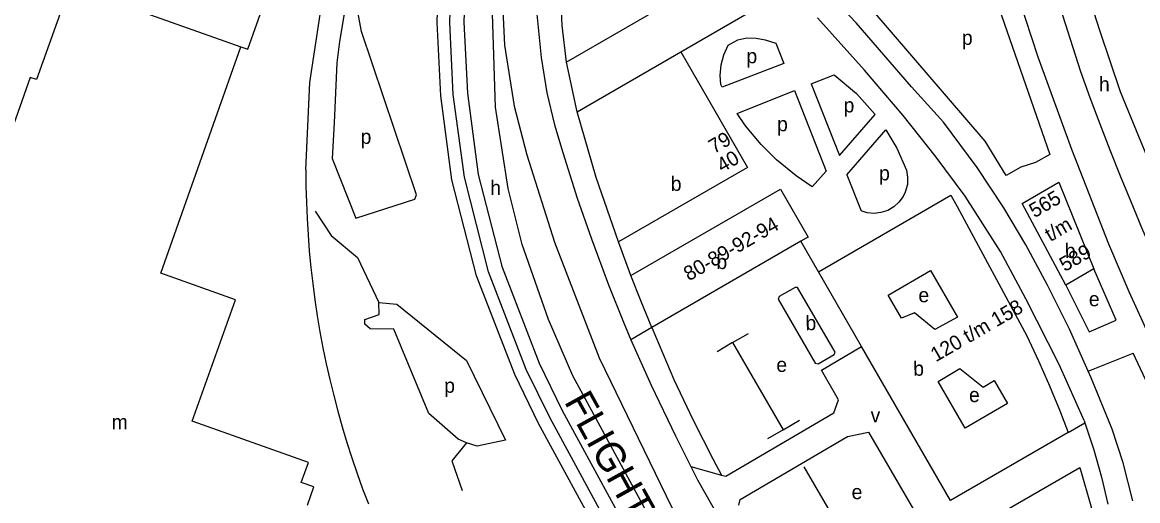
# Model space of a CAD drawing. Extents: x 154765 to 156627, y 383996 to 386132.
# Drawn here: x 155749.2 to 156057.3, y 384900.8 to 385032.8 of the extents above; entities that cross this region are included whole.
import ezdxf

# ---------------------------------------------------------------- set-up
doc = ezdxf.new("R2010")
doc.units = 0
for name, color, linetype in [('BLT_Basislijn', 7, 'Continuous'), ('BLT_Bebouwing', 7, 'Continuous'), ('BLT_Centroide', 7, 'Continuous'), ('BLT_Huisnummer_reeks', 7, 'Continuous'), ('BLT_Onderverdeling_panden', 7, 'Continuous'), ('BLT_Straatnaam_hoofdweg', 7, 'Continuous')]:
    doc.layers.add(name, color=color, linetype=linetype)

msp = doc.modelspace()

# ---------------------------------------------------------------- linework, layer by layer
at = {"layer": 'BLT_Basislijn'}
for p, q in [((156032.54, 385047.32), (156037.29, 385032.48)), ((155979.56, 385032.63), (155967.42, 385045.65)), ((155931.17, 385024.69), (155961.53, 385042.24)), ((155981.88, 385019.64), (155968.89, 385034.02)), ((155994.86, 385015), (155979.56, 385032.63)), ((156037.29, 385032.48), (156041.52, 385019.28)), ((155957.35, 385027.05), (155959.57, 385021.41)), ((155902.48, 385008.1), (155899.6, 385021.83)), ((155992.54, 385007.11), (155981.88, 385019.64)), ((155962.5, 385013.98), (155971.25, 384991.77)), ((155967.14, 385015.83), (155974.95, 384996.02)), ((156003.67, 385005.26), (155994.86, 385015)), ((155974.95, 384996.02), (155984.8, 385007.33)), ((156001.35, 384995.98), (155992.54, 385007.11)), ((156012.95, 384992.73), (156003.67, 385005.26)), ((155977.01, 384990.77), (155987.78, 385003.14)), ((156009.7, 384984.85), (156001.35, 384995.98)), ((155827.56, 384992.1), (155827.59, 384987.61)), ((155967.44, 384987.4), (155971.25, 384991.77)), ((156020.37, 384981.6), (156012.95, 384992.73)), ((155977.01, 384990.77), (155980.93, 384980.83)), ((155827.59, 384987.61), (155827.7, 384983.12)), ((155827.7, 384983.12), (155827.9, 384978.64)), ((156019.44, 384969.54), (156009.7, 384984.85)), ((156026.39, 384971.39), (156020.37, 384981.6)), ((155827.9, 384978.64), (155828.17, 384974.15)), ((155828.17, 384974.15), (155828.52, 384969.68)), ((155917.35, 384962.92), (155913.96, 384972.21)), ((155969.13, 384963.99), (155964.33, 384972.39)), ((156032.42, 384960.26), (156026.39, 384971.39)), ((155828.52, 384969.68), (155828.95, 384965.21)), ((156026.39, 384956.55), (156019.44, 384969.54)), ((155828.95, 384965.21), (155829.46, 384960.74)), ((155829.46, 384960.74), (155830.05, 384956.29)), ((156038.45, 384948.19), (156032.42, 384960.26)), ((155830.05, 384956.29), (155830.72, 384951.85)), ((156035.67, 384938.45), (156026.39, 384956.55)), ((155830.72, 384951.85), (155831.47, 384947.42)), ((155923.15, 384948.61), (155917.34, 384945.23)), ((155831.47, 384947.42), (155832.3, 384943.01)), ((155945.43, 384944.46), (155949.85, 384946.93)), ((156043.66, 384936.57), (156038.45, 384948.19)), ((155832.3, 384943.01), (155833.2, 384938.61)), ((155945.43, 384944.46), (155941.13, 384941.91)), ((155945.43, 384944.46), (155959.44, 384920.41)), ((156043.66, 384936.57), (156056.1, 384941.52)), ((155833.2, 384938.61), (155834.19, 384934.23)), ((156042.53, 384922.93), (156035.67, 384938.45)), ((156044.48, 384934.74), (156043.66, 384936.57)), ((155834.19, 384934.23), (155835.25, 384929.86)), ((156050.3, 384920.53), (156044.48, 384934.74)), ((155835.25, 384929.86), (155836.39, 384925.52)), ((155836.39, 384925.52), (155837.61, 384921.2)), ((155837.61, 384921.2), (155838.9, 384916.9)), ((155959.44, 384920.41), (155963.94, 384923.07)), ((156038.1, 384919.69), (156042.73, 384922.33)), ((156042.53, 384922.93), (156042.73, 384922.33)), ((156042.73, 384922.33), (156045.22, 384914.85)), ((155959.44, 384920.41), (155955.12, 384917.88)), ((156053.29, 384911.26), (156050.3, 384920.53)), ((155838.9, 384916.9), (155840.27, 384912.62)), ((156045.22, 384914.85), (156047.31, 384907.37)), ((155840.27, 384912.62), (155841.71, 384908.37)), ((155841.71, 384908.37), (155843.24, 384904.14)), ((155933.89, 384910.23), (155942.38, 384907.89)), ((155965.14, 384910.17), (155976.62, 384890.53)), ((156055.98, 384900.79), (156053.29, 384911.26)), ((156047.31, 384907.37), (156049.11, 384899.9)), ((155843.24, 384904.14), (155844.83, 384899.94))]:
    msp.add_line(p, q, dxfattribs=at)
for points in [[(155827.56, 384992.1), (155828.67, 385016.24), (155832.77, 385043.5), (155836.07, 385057.7), (155841.73, 385076.19), (155764.26, 385112.84)], [(155892.58, 385086.86), (155891.45, 385078.57), (155891.02, 385071.73), (155890.79, 385047.47), (155891.38, 385035.08), (155892.56, 385023.09), (155894.14, 385013.39), (155896.21, 385004.48)], [(155962.52, 384826.27), (155935.77, 384871.91), (155901.3, 384935.31), (155901.3, 384935.31), (155894.58, 384950.8), (155887.34, 384971.47), (155883.48, 384986.96), (155879.92, 385009.42), (155878.55, 385052.4), (155881.91, 385077.92)], [(155881.91, 385077.92), (155881.11, 385062.39), (155881.31, 385049.86), (155882.44, 385026.52), (155885.1, 385009.65), (155885.1, 385009.65), (155888.56, 384996.23), (155896.24, 384972.11), (155908.62, 384940.24), (155908.62, 384940.24), (155928.62, 384898.94), (155951.25, 384859.63), (155970.21, 384827.91), (155980.73, 384813.62), (155980.73, 384813.62)], [(156061.74, 384943.77), (156054.93, 384958.46), (156049.32, 384971.64), (156039.1, 384997.76), (156029.81, 385023.21), (156021.05, 385049.93), (156014.47, 385072.85)], [(155982.74, 384747.99), (155981.79, 384761.81), (155978.09, 384773), (155961.45, 384799.64), (155934.97, 384845.54), (155909.95, 384888.82), (155891.81, 384922.17), (155885.25, 384935.64), (155874.71, 384962.88), (155867.9, 384989.38), (155864.81, 385012.56), (155863.83, 385032.74), (155864.43, 385050.58)], [(155965.34, 384800.02), (155964.45, 384801.44), (155938, 384847.29), (155913, 384890.54), (155894.92, 384923.78), (155888.46, 384937.04), (155878.05, 384963.95), (155871.35, 384990.05), (155868.3, 385012.88), (155867.33, 385032.77), (155867.93, 385050.46)], [(155968.54, 384801.65), (155941.46, 384849.29), (155916.49, 384892.49), (155898.47, 384925.61), (155892.13, 384938.64), (155881.86, 384965.17), (155875.28, 384990.81), (155872.29, 385013.24), (155871.33, 385032.8), (155871.93, 385050.32)], [(156015.93, 385045.61), (156033.06, 384996.37), (156029.14, 384994.1), (156025.03, 384992.84), (156021.02, 384990.55), (156015.24, 385000), (155984.29, 385035.94)], [(156136, 384858.96), (156115.57, 384891.11), (156096.29, 384922.61), (156080.28, 384952.51), (156069.18, 384974.46), (156063, 384988.46), (156057.67, 385001.26), (156052.62, 385013.66), (156046.98, 385030.26), (156042.75, 385043.48)], [(155959.57, 385021.41), (155942.59, 385014.88), (155942.15, 385015.66), (155941.98, 385018.14), (155942.26, 385021.1), (155943.01, 385023.86), (155944.21, 385026.46), (155946.84, 385027.98), (155949.37, 385028.48), (155951.98, 385028.47), (155954.4, 385027.96), (155957.35, 385027.05)], [(156041.52, 385019.28), (156044.14, 385012.03), (156046.84, 385004.82), (156049.62, 384997.63), (156052.47, 384990.47), (156055.39, 384983.34), (156058.39, 384976.24), (156061.46, 384969.18), (156064.6, 384962.14), (156067.82, 384955.14), (156071.11, 384948.18), (156074.47, 384941.24), (156077.9, 384934.35), (156081.41, 384927.48), (156084.99, 384920.66), (156088.63, 384913.87), (156092.35, 384907.12), (156095.68, 384901.22)], [(155967.14, 385015.83), (155973.46, 385018.35), (155979.63, 385013.14), (155984.8, 385007.33)], [(155967.44, 384987.4), (155962.98, 384990.41), (155957.55, 384994.85), (155953.29, 384999.07), (155948.97, 385004.24), (155946.74, 385007.69), (155962.5, 385013.98)], [(155896.21, 385004.48), (155898.51, 384996.87), (155902.55, 384984.3), (155906.47, 384973.07), (155911.19, 384960.36), (155915.31, 384950.04), (155917.34, 384945.23)], [(155987.78, 385003.14), (155990.76, 384998.07), (155993.45, 384992), (155993.79, 384990.04), (155993.71, 384988.1), (155993.13, 384985.95), (155992.53, 384984.73), (155991.37, 384983.16), (155989.94, 384981.87), (155988.28, 384980.92), (155986.42, 384980.31), (155984.56, 384980.1), (155982.62, 384980.29), (155980.93, 384980.83)], [(155830.1, 384980.75), (155834.6, 384974), (155841.8, 384967.92), (155847.72, 384955.47)], [(156037.46, 384960.3), (156043.92, 384947.46), (156051.35, 384950.63), (156045.21, 384964.78)], [(155871.92, 384916.82), (155869.67, 384917.77), (155861.57, 384924.92), (155851.84, 384948.19), (155845.31, 384948.24), (155843.87, 384949.5), (155843.84, 384950.84), (155847.79, 384952.22), (155847.72, 384955.47)], [(155847.72, 384955.47), (155852.69, 384955.07), (155871.91, 384939.53), (155882.7, 384917.5), (155874.93, 384915.89), (155871.92, 384916.82)], [(155923.15, 384948.61), (155929.17, 384934.24), (155934.53, 384923.04), (155939.97, 384912.36), (155942.38, 384907.89)], [(155917.34, 384945.23), (155922.9, 384932.71), (155929.65, 384918.72), (155933.89, 384910.23)], [(155942.38, 384907.89), (155943.56, 384907.56), (155973.41, 384925.06), (155974.69, 384928.7), (155969.95, 384936.86), (155981.05, 384943.38)], [(156065.34, 384815.35), (156069.84, 384817.65), (156076.45, 384821.69), (156082.14, 384826.94), (156086.82, 384832.59), (156090.38, 384838.99), (156091.74, 384842.55), (156092.79, 384846.44), (156093.42, 384850.35), (156093.66, 384854.23), (156092.91, 384861.91), (156091.4, 384869.47), (156089.18, 384876.95), (156086.34, 384884.21), (156078.11, 384900.51), (156063.66, 384925.43), (156056.1, 384941.52)], [(155947.12, 384899.61), (155947.5, 384901.16), (155977.2, 384918.58), (155983.01, 384919.78), (155997.35, 384895.09), (155982.3, 384886.45), (155983.87, 384882.97), (155964.19, 384869.82)], [(155871.92, 384916.82), (155867.9, 384911.8), (155870.71, 384903.68)], [(155933.89, 384910.23), (155935.71, 384906.61), (155943.51, 384892.95), (155944.9, 384890.58)]]:
    msp.add_lwpolyline(points, dxfattribs=at)
msp.add_lwpolyline([(155840.44, 385043.65), (155838.09, 385034.59), (155836.86, 385027.54), (155836.08, 385021.6), (155835.43, 385005.08), (155834.83, 384995.23), (155841.38, 384978.78), (155857.63, 384984), (155858.17, 384985.25), (155842.94, 385030.24)], close=True, dxfattribs=at)
at = {"layer": 'BLT_Bebouwing'}
msp.add_line((156045.22, 384964.78), (156037.46, 384960.3), dxfattribs=at)
for points in [[(155809.65, 385026.03), (155811.53, 385025.36), (155824.79, 385062.76), (155777.02, 385090.13)], [(155899.6, 385021.83), (155898.36, 385031.96), (155897.72, 385045.37), (155897.61, 385063.18), (155898.17, 385073.01), (155898.47, 385075.8)], [(155898.47, 385075.8), (155907.47, 385071.11), (155922.15, 385062.79), (155935.76, 385054.02), (155940.18, 385050.9), (155944.6, 385047.79), (155899.6, 385021.83)], [(155762.36, 385042.82), (155753.18, 385017), (155751.43, 385017.62), (155744.64, 384998.23), (155746.3, 384997.64), (155740.17, 384980.4), (155738.59, 384980.96), (155696.77, 384862.93)], [(155827.99, 384899.57), (155829.8, 384904.65), (155826.31, 384905.89), (155828.26, 384911.34), (155796.18, 384922.73), (155808.14, 384956.27), (155787.49, 384963.57), (155809.65, 385026.03)], [(155902.48, 385008.1), (155931.17, 385024.69)], [(155931.17, 385024.69), (155949.58, 384992.77), (155913.96, 384972.21)], [(155913.96, 384972.21), (155907.76, 384989.99), (155902.48, 385008.1)], [(156037.46, 384960.3), (156025.39, 384982.81), (156035.57, 384988.69), (156045.22, 384964.78)], [(155917.35, 384962.92), (155958.63, 384986.76), (155966.28, 384973.52), (155965.8, 384973.23), (155964.33, 384972.39)], [(155969.13, 384963.99), (156005.74, 384985.14)], [(156005.74, 384985.14), (156007.45, 384982), (156026.73, 384946.33), (156029.93, 384939.46), (156032.74, 384933.14), (156035.72, 384925.89), (156038.1, 384919.69)], [(155964.33, 384972.39), (155923.15, 384948.61)], [(155981.05, 384943.38), (155969.13, 384963.99)], [(155923.15, 384948.61), (155920.18, 384955.74), (155917.35, 384962.92)], [(156038.1, 384919.69), (156005.6, 384900.89), (155981.05, 384943.38)]]:
    msp.add_lwpolyline(points, dxfattribs=at)
for points in [[(155988.42, 384957.57), (156000.13, 384964.36), (156007.58, 384951.42), (156001.34, 384948.08), (155995.68, 384952.66), (155992.13, 384951.17)], [(155962.71, 384959.68), (155958.3, 384957.12), (155958.04, 384956.47), (155968.28, 384938.8), (155969.04, 384938.59), (155973.45, 384941.15), (155973.74, 384941.81), (155963.38, 384959.64)], [(156002.2, 384933.75), (156008.23, 384937.27), (156014.63, 384932.16), (156017.67, 384933.97), (156021.33, 384927.65), (156009.65, 384920.87)], [(155994.96, 384883.21), (156041.37, 384910), (156044.59, 384898.79), (156047.23, 384887.42), (156006.21, 384863.74)]]:
    msp.add_lwpolyline(points, close=True, dxfattribs=at)
at = {"layer": 'BLT_Onderverdeling_panden'}
msp.add_line((155762.36, 385042.82), (155809.65, 385026.03), dxfattribs=at)

# ---------------------------------------------------------------- texts
at = {"layer": 'BLT_Centroide'}
for s, p in [('p', (156008.77, 385026.58)), ('p', (155949.26, 385021.5)), ('h', (156046.64, 385013.74)), ('p', (155976.1, 385007.95)), ('p', (155957.72, 385002.75)), ('p', (155842.69, 384999.25)), ('p', (155985.9, 384989.2)), ('h', (155878.49, 384985.16)), ('e', (155996.77, 384955.58)), ('e', (156043.84, 384954.47)), ('e', (155957.52, 384936.36)), ('p', (155865.78, 384930.61)), ('e', (156010.74, 384928.04)), ('v', (155983.55, 384922.45)), ('m', (155773.92, 384920.53)), ('e', (155978.31, 384901.26))]:
    msp.add_text(s, height=4, dxfattribs=at).set_placement(p)
for p in [(155928.38, 384986.27), (156037.24, 384967.78), (155940.99, 384964.7), (155965.6, 384947.85), (155995.35, 384935.28)]:
    msp.add_text('b', height=4, rotation=1, dxfattribs=at).set_placement(p)
at = {"layer": 'BLT_Huisnummer_reeks'}
for s, rotation, p in [('79', 29.9998, (155940.28, 384996.43)), ('40', 29.9998, (155942.53, 384991.25)), ('565', 30.0033, (156028.81, 384978.74)), ('80-89-92-94', 29.997, (155933.37, 384961.32)), ('t/m', 30.0033, (156033.16, 384972.17)), ('589', 30.0033, (156037.19, 384963.88)), ('120 t/m 158', 29.9991, (156001.58, 384939))]:
    msp.add_text(s, height=4, rotation=rotation, dxfattribs=at).set_placement(p)
at = {"layer": 'BLT_Straatnaam_hoofdweg'}
msp.add_text('FLIGHT FORUM', height=8, rotation=299, dxfattribs=at).set_placement((155898.78, 384928.19))

doc.saveas('drawing.dxf')
